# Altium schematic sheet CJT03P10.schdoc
size 127 x 101 mm
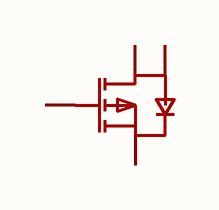
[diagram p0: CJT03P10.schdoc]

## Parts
Q?  cjt03p10  [SOT-223-3_L6.7-W3.7-P2.30-LS7.0-BR]  (value not drawn)

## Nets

Not connected (* = marked no-connect by the designer): Q? 1(G) 2(D) 3(S) 4(D)

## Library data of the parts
Q? = cjt03p10: 数量:1个P沟道;漏源电压(Vdss):100V;连续漏极电流(Id):3A;导通电阻(RDS(on)):190mΩ@10V;耗散功率(Pd):3.1W;阈值电压(Vgs(th)):3V;; Manufacturer: CJ(江苏长电/长晶); AddInBom: yes; ModelId: aa95d8a488c542b6aa3117a8a473808d; ModelTransform: 271.653,263.779,0,0,0,0,0,0,0; Number: 1个P沟道; Drain to Source Voltage: 100V; Current - Continuous Drain(Id): 3A; Pd - Power Dissipation: 3.1W; Gate Threshold Voltage (Vgs(th)): 3V; Gate Charge(Qg): 40nC@4.5V; Input Capacitance(Ciss): 2.5nF; Reverse Transfer Capacitance (Crss@Vds): 90pF; Output Capacitance(Coss): 170pF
